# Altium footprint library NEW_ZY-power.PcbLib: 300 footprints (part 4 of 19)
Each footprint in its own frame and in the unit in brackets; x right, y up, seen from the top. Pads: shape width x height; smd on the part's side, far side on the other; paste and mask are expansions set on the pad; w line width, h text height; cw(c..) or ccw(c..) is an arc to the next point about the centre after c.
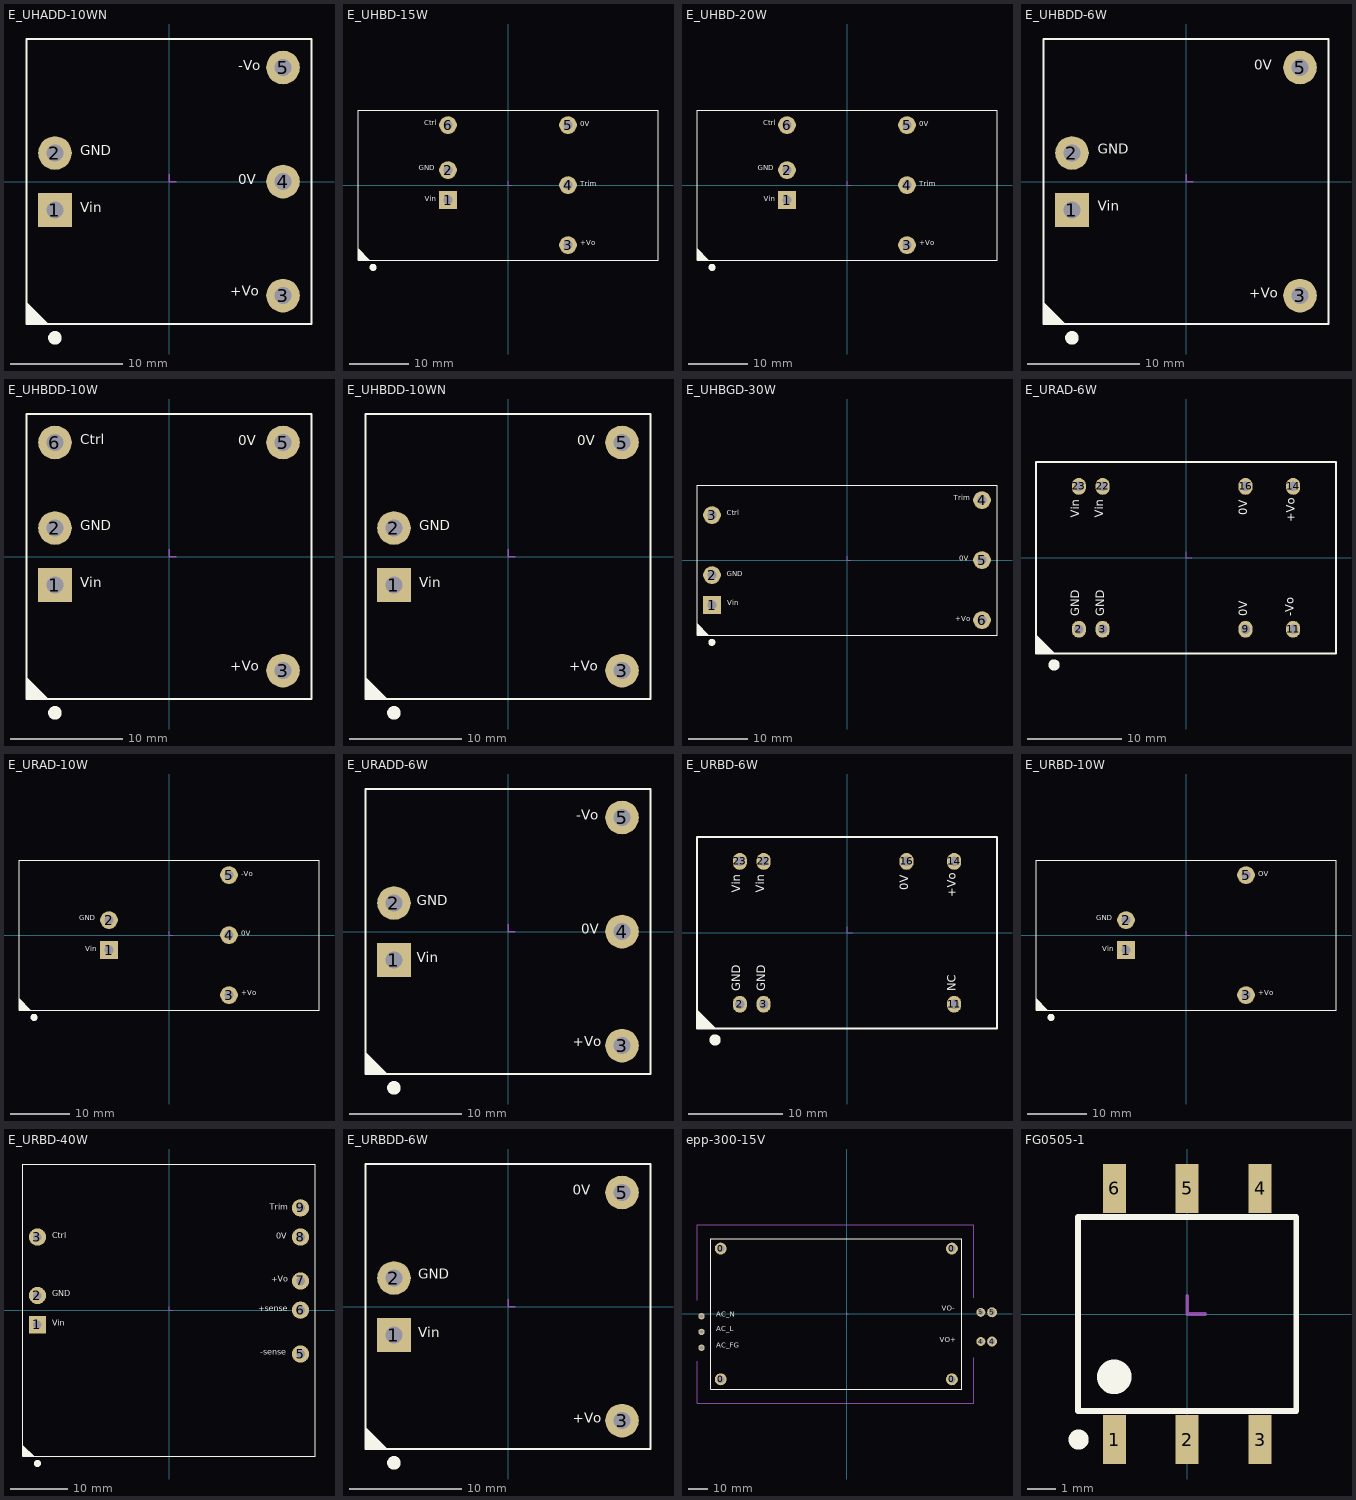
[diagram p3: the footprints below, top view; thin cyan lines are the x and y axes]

## E_UHADD-10WN [mm]
height 11.7
pads (5):
  rect 3x3 hole 1.5: 1(-10.16,-2.54)
  round 3 hole 1.5: 2(-10.16,2.54) 3(10.16,-10.16) 4(10.16,0) 5(10.16,10.16)
Top Overlay:
  circle w1: c-10.16,-13.925 r0.1
  region: -12.7,-12.7 -10.725,-12.7 -12.7,-10.725
  lines w0.2: -12.7,-12.7 -12.7,12.7 12.7,12.7 12.7,-12.7 -12.7,-12.7
  text "0V" at 6.175,-0.535 h1.52
  text "GND" at -7.901,2.05 h1.52
  text "Vin" at -7.9,-3.025 h1.52
  text "+Vo" at 5.435,-10.5 h1.52
  text "-Vo" at 6.175,9.625 h1.52
Mechanical 15:
  lines w0.127: 0,0.635 0,0 0.635,0

## E_UHBD-15W [mm]
pads (6):
  rect 3x3 hole 1.5: 1(-10.16,-2.54)
  round 3 hole 1.5: 2(-10.16,2.54) 3(10.16,-10.16) 4(10.16,0) 5(10.16,10.16) 6(-10.16,10.16)
Top Overlay:
  circle w1: c-22.86,-13.925 r0.1
  region: -25.4,-12.7 -23.425,-12.7 -25.4,-10.725
  lines w0.2: -25.4,-12.7 -25.4,12.7 25.4,12.7 25.4,-12.7 -25.4,-12.7
  text "+Vo" at 12.192,-10.541 h1.52
  text "0V" at 12.192,9.652 h1.52
  text "GND" at -15.113,2.159 h1.52
  text "Vin" at -14.103,-3.048 h1.52
  text "Trim" at 12.192,-0.508 h1.52
  text "Ctrl" at -14.187,9.779 h1.52
Mechanical 15:
  lines w0.127: 0,0.635 0,0 0.635,0

## E_UHBD-20W [mm]
pads (6):
  rect 3x3 hole 1.5: 1(-10.16,-2.54)
  round 3 hole 1.5: 2(-10.16,2.54) 3(10.16,-10.16) 4(10.16,0) 5(10.16,10.16) 6(-10.16,10.16)
Top Overlay:
  circle w1: c-22.86,-13.925 r0.1
  region: -25.4,-12.7 -23.425,-12.7 -25.4,-10.725
  lines w0.2: -25.4,-12.7 -25.4,12.7 25.4,12.7 25.4,-12.7 -25.4,-12.7
  text "Ctrl" at -14.187,9.779 h1.52
  text "Trim" at 12.192,-0.508 h1.52
  text "Vin" at -14.103,-3.048 h1.52
  text "GND" at -15.113,2.159 h1.52
  text "0V" at 12.192,9.652 h1.52
  text "+Vo" at 12.192,-10.541 h1.52
Mechanical 15:
  lines w0.127: 0,0.635 0,0 0.635,0

## E_UHBDD-6W [mm]
height 11.7
pads (4):
  rect 3x3 hole 1.5: 1(-10.16,-2.54)
  round 3 hole 1.5: 2(-10.16,2.54) 3(10.16,-10.16) 5(10.16,10.16)
Top Overlay:
  circle w1: c-10.16,-13.925 r0.1
  region: -12.7,-12.7 -10.725,-12.7 -12.7,-10.725
  lines w0.2: -12.7,-12.7 -12.7,12.7 12.7,12.7 12.7,-12.7 -12.7,-12.7
  text "Vin" at -7.873,-2.921 h1.52
  text "GND" at -7.874,2.159 h1.52
  text "0V" at 6.096,9.652 h1.52
  text "+Vo" at 5.649,-10.668 h1.52
Mechanical 15:
  lines w0.127: 0,0.635 0,0 0.635,0

## E_UHBDD-10W [mm]
height 11.7
pads (5):
  rect 3x3 hole 1.5: 1(-10.16,-2.54)
  round 3 hole 1.5: 2(-10.16,2.54) 3(10.16,-10.16) 5(10.16,10.16) 6(-10.16,10.16)
Top Overlay:
  circle w1: c-10.16,-13.925 r0.1
  region: -12.7,-12.7 -10.725,-12.7 -12.7,-10.725
  lines w0.2: -12.7,-12.7 -12.7,12.7 12.7,12.7 12.7,-12.7 -12.7,-12.7
  text "GND" at -7.901,2.05 h1.52
  text "Vin" at -7.9,-3.025 h1.52
  text "Ctrl" at -7.901,9.7 h1.52
  text "+Vo" at 5.435,-10.5 h1.52
  text "0V" at 6.175,9.625 h1.52
Mechanical 15:
  lines w0.127: 0,0.635 0,0 0.635,0

## E_UHBDD-10WN [mm]
height 11.7
pads (4):
  rect 3x3 hole 1.5: 1(-10.16,-2.54)
  round 3 hole 1.5: 2(-10.16,2.54) 3(10.16,-10.16) 5(10.16,10.16)
Top Overlay:
  circle w1: c-10.16,-13.925 r0.1
  region: -12.7,-12.7 -10.725,-12.7 -12.7,-10.725
  lines w0.2: -12.7,-12.7 12.7,-12.7 12.7,12.7 -12.7,12.7 -12.7,-12.7
  text "0V" at 6.175,9.625 h1.52
  text "+Vo" at 5.435,-10.5 h1.52
  text "Vin" at -7.9,-3.025 h1.52
  text "GND" at -7.901,2.05 h1.52
Mechanical 15:
  lines w0.127: 0,0.635 0,0 0.635,0

## E_UHBGD-30W [mm]
height 12.7
pads (6):
  rect 3x3 hole 1.5: 1(-22.86,-7.62)
  round 3 hole 1.5: 2(-22.86,-2.54) 3(-22.86,7.62) 4(22.86,10.16) 5(22.86,0) 6(22.86,-10.16)
Top Overlay:
  circle w1: c-22.887,-13.925 r0.1
  region: -25.4,-12.7 -23.425,-12.7 -25.4,-10.725
  lines w0.2: -25.4,-12.7 -25.4,12.7 25.4,12.7 25.4,-12.7 -25.4,-12.7
  text "+Vo" at 18.301,-10.668 h1.52
  text "0V" at 19.041,-0.445 h1.52
  text "GND" at -20.321,-3.048 h1.52
  text "Vin" at -20.32,-8.001 h1.52
  text "Trim" at 18.034,9.779 h1.52
  text "Ctrl" at -20.321,7.239 h1.52
Mechanical 15:
  lines w0.127: 0,0.635 0,0 0.635,0

## E_URAD-6W [mm]
height 11
pads (8):
  oval 1.5x1.8 hole 1: 2(-11.43,-7.62) 3(-8.89,-7.62) 9(6.35,-7.62) 11(11.43,-7.62) 14(11.43,7.62) 16(6.35,7.62) 22(-8.89,7.62) 23(-11.43,7.62)
Top Overlay:
  circle w1: c-14.072,-11.425 r0.1
  region: -16,-10.2 -14.025,-10.2 -16,-8.225
  lines w0.2: -16,-10.2 16,-10.2 16,10.2 -16,10.2 -16,-10.2
  text "0V" at 6.833,-6.223 h1.52
  text "0V" at 6.858,4.55 h1.52
  text "+Vo" at 11.938,3.81 h1.52
  text "-Vo" at 11.811,-6.223 h1.52
  text "Vin" at -8.509,4.278 h1.52
  text "Vin" at -11.049,4.278 h1.52
  text "GND" at -8.382,-6.223 h1.52
  text "GND" at -11.049,-6.223 h1.52
Mechanical 15:
  lines w0.127: 0,0.635 0,0 0.635,0

## E_URAD-10W [mm]
height 12.7
pads (5):
  rect 3x3 hole 1.5: 1(-10.16,-2.54)
  round 3 hole 1.5: 2(-10.16,2.54) 3(10.16,-10.16) 4(10.16,0) 5(10.16,10.16)
Top Overlay:
  circle w1: c-22.86,-13.925 r0.1
  region: -25.4,-12.7 -23.425,-12.7 -25.4,-10.725
  lines w0.2: -25.4,-12.7 -25.4,12.7 25.4,12.7 25.4,-12.7 -25.4,-12.7
  text "+Vo" at 12.192,-10.541 h1.52
  text "-Vo" at 12.192,9.652 h1.52
  text "GND" at -15.189,2.159 h1.52
  text "Vin" at -14.179,-3.048 h1.52
  text "0V" at 12.192,-0.483 h1.52
Mechanical 15:
  lines w0.127: 0,0.635 0,0 0.635,0

## E_URADD-6W [mm]
height 11.7
pads (5):
  rect 3x3 hole 1.5: 1(-10.16,-2.54)
  round 3 hole 1.5: 2(-10.16,2.54) 3(10.16,-10.16) 4(10.16,0) 5(10.16,10.16)
Top Overlay:
  circle w1: c-10.16,-13.925 r0.1
  region: -12.7,-12.7 -10.725,-12.7 -12.7,-10.725
  lines w0.2: -12.7,-12.7 12.7,-12.7 12.7,12.7 -12.7,12.7 -12.7,-12.7
  text "+Vo" at 5.764,-10.541 h1.52
  text "-Vo" at 6.076,9.652 h1.52
  text "0V" at 6.504,-0.508 h1.52
  text "GND" at -8.139,2.032 h1.52
  text "Vin" at -8.137,-3.048 h1.52
Mechanical 15:
  lines w0.127: 0,0.635 0,0 0.635,0

## E_URBD-6W [mm]
height 11
pads (7):
  oval 1.5x1.8 hole 1: 2(-11.43,-7.62) 3(-8.89,-7.62) 11(11.43,-7.62) 14(11.43,7.62) 16(6.35,7.62) 22(-8.89,7.62) 23(-11.43,7.62)
Top Overlay:
  circle w1: c-14.072,-11.425 r0.1
  region: -16,-10.2 -14.025,-10.2 -16,-8.225
  lines w0.2: -16,-10.2 -16,10.2 16,10.2 16,-10.2 -16,-10.2
  text "GND" at -11.049,-6.223 h1.52
  text "GND" at -8.382,-6.223 h1.52
  text "Vin" at -11.049,4.278 h1.52
  text "Vin" at -8.509,4.278 h1.52
  text "NC" at 11.938,-6.223 h1.52
  text "+Vo" at 11.938,3.81 h1.52
  text "0V" at 6.858,4.55 h1.52
Mechanical 15:
  lines w0.127: 0,0.635 0,0 0.635,0

## E_URBD-10W [mm]
height 12.7
pads (4):
  rect 3x3 hole 1.5: 1(-10.16,-2.54)
  round 3 hole 1.5: 2(-10.16,2.54) 3(10.16,-10.16) 5(10.16,10.16)
Top Overlay:
  circle w1: c-22.86,-13.925 r0.1
  region: -25.4,-12.7 -23.425,-12.7 -25.4,-10.725
  lines w0.2: -25.4,-12.7 25.4,-12.7 25.4,12.7 -25.4,12.7 -25.4,-12.7
  text "Vin" at -14.179,-3.048 h1.52
  text "GND" at -15.189,2.159 h1.52
  text "OV" at 12.192,9.652 h1.52
  text "+Vo" at 12.192,-10.541 h1.52
Mechanical 15:
  lines w0.127: 0,0.635 0,0 0.635,0

## E_URBD-40W [mm]
height 11.2
pads (8):
  rect 3x3 hole 1.5: 1(-22.86,-2.54)
  round 3 hole 1.5: 2(-22.86,2.54) 3(-22.86,12.7) 5(22.86,-7.62) 6(22.86,0) 7(22.86,5.08) 8(22.86,12.7) 9(22.86,17.78)
Top Overlay:
  circle w1: c-22.86,-26.625 r0.1
  region: -25.4,-25.4 -23.425,-25.4 -25.4,-23.425
  lines w0.2: -25.4,-25.4 25.4,-25.4 25.4,25.4 -25.4,25.4 -25.4,-25.4
  text "Trim" at 17.475,17.145 h1.78
  text "Ctrl" at -20.322,12.194 h1.78
  text "-sense" at 15.858,-8.128 h1.78
  text "+sense" at 15.494,-0.508 h1.78
  text "Vin" at -20.32,-3.046 h1.78
  text "GND" at -20.322,2.034 h1.78
  text "0V" at 18.651,12.065 h1.78
  text "+Vo" at 17.787,4.572 h1.78
Mechanical 15:
  lines w0.127: 0,0.635 0,0 0.635,0

## E_URBDD-6W [mm]
height 11.7
pads (4):
  rect 3x3 hole 1.5: 1(-10.16,-2.54)
  round 3 hole 1.5: 2(-10.16,2.54) 3(10.16,-10.16) 5(10.16,10.16)
Top Overlay:
  circle w1: c-10.16,-13.925 r0.1
  region: -12.7,-12.7 -10.725,-12.7 -12.7,-10.725
  lines w0.2: -12.7,-12.7 12.7,-12.7 12.7,12.7 -12.7,12.7 -12.7,-12.7
  text "+Vo" at 5.764,-10.668 h1.52
  text "0V" at 5.764,9.652 h1.52
  text "GND" at -8.012,2.159 h1.52
  text "Vin" at -8.01,-3.048 h1.52
Mechanical 15:
  lines w0.127: 0,0.635 0,0 0.635,0

## epp-300-15V [mm]
height 22
pads (11):
  round 6 hole 3.6: 0(-63.785,-33.1) 0(-63.785,33.1) 0(53.215,-33.1) 0(53.215,33.1)
  round 3.2 hole 1.8: 1(-73.516,-1.134) 2(-73.516,-9.08) 3(-73.516,-17.076)
  round 4.5 hole 2.5: 4(67.846,-13.956) 5(67.846,0.813)
  round 5 hole 3.2: 4(73.516,-13.95) 5(73.516,0.825)
Top Overlay:
  lines w0.2: -68.785,-38.1 -68.785,38.1 58.215,38.1 58.215,-38.1 -68.785,-38.1
  text "AC_L" at -65.938,-9.779 h4.5
  text "AC_N" at -65.938,-2.311 h4.5
  text "AC_FG" at -65.938,-18.11 h4.5
  text "VO-" at 48.022,0.508 h4.5
  text "VO+" at 47.117,-15.367 h4.5
Mechanical 15:
  lines w0.127: 0,0.635 0,0 0.635,0
  lines w0.203: -75.785,-45.1 -75.785,-23.9 ; -75.785,6.875 -75.785,12.15 ; -75.785,11.7 -75.785,25.875 ; -75.785,25.675 -75.785,45.025 ; -75.785,45.05 -47.735,45.05 -33.56,45.05 64.191,45.05 ; -75.735,-45.1 -56.06,-45.1 -41.885,-45.1 64.191,-45.1 64.191,-22.175 ; 64.191,8.2 64.191,24.575 ; 64.191,24.275 64.191,45.026

## FG0505-1 [mm]
height 5.25
pads (6):
  rect 0.8x1.7 smd: 1(-2.54,-4.375) 2(0,-4.375) 3(2.54,-4.375) 4(2.54,4.375) 5(0,4.375) 6(-2.54,4.375)
Top Overlay:
  circle w1: c-2.54,-2.189 r0.1
  circle w0.5: c-3.783,-4.375 r0.1
  lines w0.2: -3.8,-3.375 -3.8,3.375 3.8,3.375 3.8,-3.375 -3.8,-3.375
Mechanical 15:
  lines w0.127: 0,0.635 0,0 0.635,0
